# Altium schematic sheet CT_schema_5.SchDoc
size 287 x 163 mm
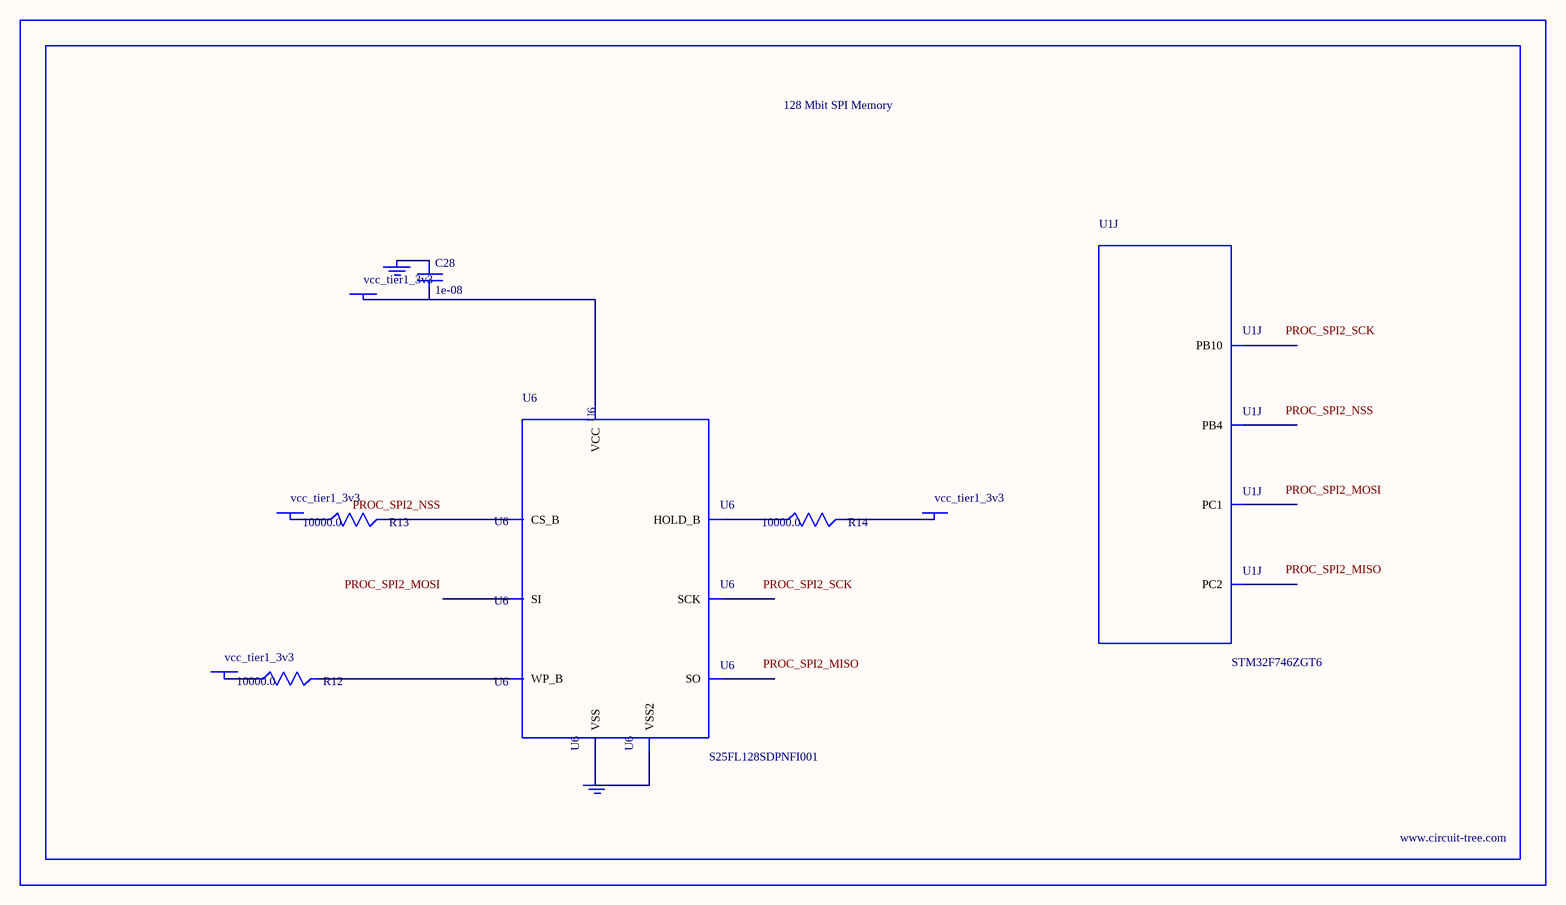
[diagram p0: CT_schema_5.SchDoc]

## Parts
BORDER4  (no value)
C28  1e-08  [C0402]
GND_INSTANCE_4_0  (no value)
GND_INSTANCE_4_1  (no value)
POWER_INSTANCE_4_0  vcc_tier1_3v3
POWER_INSTANCE_4_1  vcc_tier1_3v3
POWER_INSTANCE_4_2  vcc_tier1_3v3
POWER_INSTANCE_4_3  vcc_tier1_3v3
R12  10000.0  [R0603]
R13  10000.0  [R0603]
R14  10000.0  [R0603]
U1  STM32F746ZGT6  [LQFP144]  (part J of 12)
U6  S25FL128SDPNFI001  [WNG008]

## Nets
NetC28_1: C28.1 GND_INSTANCE_4_0.0(GND)
NetC28_2: C28.2 POWER_INSTANCE_4_3.0(PWR) U6.8(VCC)
NetGND_INSTANCE_4_1_0: GND_INSTANCE_4_1.0(GND) U6.4(VSS) U6.PAD(VSS2)
NetPOWER_INSTANCE_4_0_0: POWER_INSTANCE_4_0.0(PWR) R13.1
NetPOWER_INSTANCE_4_1_0: POWER_INSTANCE_4_1.0(PWR) R12.1
NetPOWER_INSTANCE_4_2_0: POWER_INSTANCE_4_2.0(PWR) R14.2
NetR12_2: R12.2 U6.3(WP_B)
NetR13_2: R13.2 U6.1(CS_B)
NetR14_1: R14.1 U6.7(HOLD_B)

Not connected (* = marked no-connect by the designer): U1 27(PC1) 28(PC2) 69(PB10) 134(PB4); U6 2(SO) 5(SI) 6(SCK)

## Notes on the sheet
- Labels drawn without touching a wire or pin: PROC_SPI2_MISO, PROC_SPI2_MOSI, PROC_SPI2_NSS, PROC_SPI2_SCK

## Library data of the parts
BORDER4 = BORDER_PAGE4
C28 = C0402C103K3RAC
GND_INSTANCE_4_0 GND_INSTANCE_4_1 = GND
POWER_INSTANCE_4_0-POWER_INSTANCE_4_3 = PWR
R12-R14 = RC0603JR-0710KL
